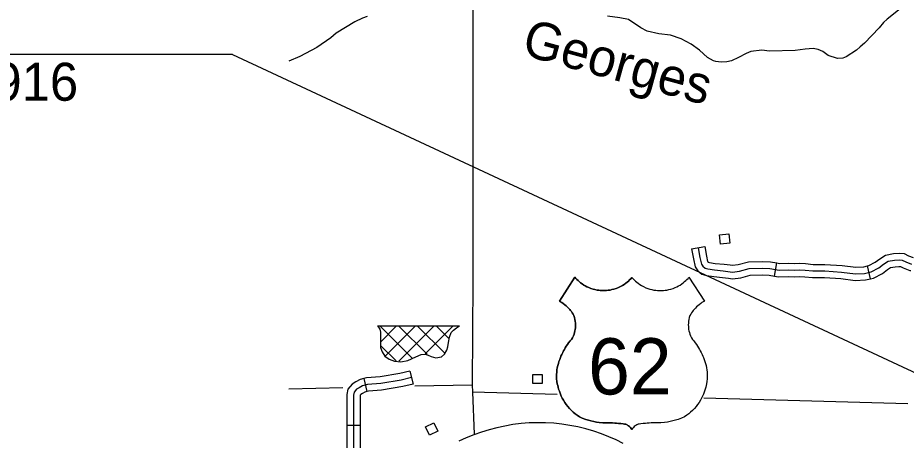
# Model space of a CAD drawing. Extents: x 1370130 to 1380143, y 377636 to 380256.
# Drawn here: x 1377914.6 to 1378335.4, y 378462.7 to 378662.8 of the extents above; entities that cross this region are included whole.
import ezdxf

# ---------------------------------------------------------------- set-up
doc = ezdxf.new("R2010")
doc.units = 0
for name, color, linetype in [('Level 15', 7, 'Continuous'), ('Level 22', 7, 'Continuous'), ('Level 32', 7, 'Continuous'), ('Level 35', 7, 'Continuous'), ('Level 4', 7, 'Continuous'), ('Level 45', 7, 'Continuous'), ('Level 49', 7, 'Continuous'), ('Level 5', 7, 'Continuous'), ('Level 56', 7, 'Continuous'), ('Level 57', 7, 'Continuous'), ('R_Draft', 7, 'Continuous')]:
    doc.layers.add(name, color=color, linetype=linetype)

msp = doc.modelspace()

# ---------------------------------------------------------------- linework, layer by layer
at = {"layer": 'Level 15'}
for p, q in [((1378141.58, 378468.6), (1378137.87, 378467.62)), ((1378145.34, 378469.44), (1378141.58, 378468.6)), ((1378149.13, 378470.1), (1378145.34, 378469.44)), ((1378152.96, 378470.61), (1378149.13, 378470.1)), ((1378156.85, 378470.92), (1378152.96, 378470.61)), ((1378160.73, 378471.03), (1378156.85, 378470.92)), ((1378164.6, 378470.97), (1378160.73, 378471.03)), ((1378168.46, 378470.73), (1378164.6, 378470.97)), ((1378172.31, 378470.32), (1378168.46, 378470.73)), ((1378176.13, 378469.75), (1378172.31, 378470.32)), ((1378179.92, 378469.01), (1378176.13, 378469.75)), ((1378183.68, 378468.09), (1378179.92, 378469.01)), ((1378187.39, 378467.01), (1378183.68, 378468.09)), ((1378127.03, 378463.78), (1378123.54, 378462.23)), ((1378130.58, 378465.2), (1378127.03, 378463.78)), ((1378134.2, 378466.48), (1378130.58, 378465.2)), ((1378137.87, 378467.62), (1378134.2, 378466.48)), ((1378191.01, 378465.76), (1378187.39, 378467.01)), ((1378194.53, 378464.38), (1378191.01, 378465.76)), ((1378197.97, 378462.87), (1378194.53, 378464.38)), ((1378201.34, 378461.25), (1378197.97, 378462.87))]:
    msp.add_line(p, q, dxfattribs=at)
at = {"layer": 'Level 22'}
for points in [[(1378205.49, 378539.84), (1378204.93, 378539.22), (1378204.41, 378538.68), (1378203.81, 378538.12), (1378203.16, 378537.56), (1378202.53, 378537.08), (1378201.77, 378536.55), (1378200.96, 378536.04), (1378200.03, 378535.53), (1378198.86, 378534.98), (1378197.95, 378534.63), (1378196.93, 378534.3), (1378196, 378534.06), (1378195.14, 378533.88), (1378194.23, 378533.74), (1378193.4, 378533.66), (1378192.26, 378533.6), (1378191.33, 378533.61), (1378190.52, 378533.66), (1378189.75, 378533.75), (1378188.97, 378533.86), (1378187.99, 378534.06), (1378187.08, 378534.3), (1378185.98, 378534.66), (1378185.04, 378535.03), (1378184.19, 378535.42), (1378183.41, 378535.83), (1378182.69, 378536.25), (1378181.89, 378536.78), (1378181.15, 378537.32), (1378180.52, 378537.84), (1378179.98, 378538.31), (1378179.43, 378538.84), (1378178.9, 378539.41), (1378178.46, 378539.9), (1378171.19, 378528.66), (1378171.71, 378528.35), (1378172.33, 378527.95), (1378172.92, 378527.53), (1378173.7, 378526.92), (1378174.32, 378526.39), (1378174.87, 378525.87), (1378175.44, 378525.3), (1378176.01, 378524.66), (1378176.43, 378524.16), (1378176.84, 378523.63), (1378177.25, 378523.05), (1378177.65, 378522.44), (1378178.02, 378521.73), (1378178.31, 378520.85), (1378178.52, 378519.99), (1378178.68, 378519.06), (1378178.77, 378518.2), (1378178.8, 378517.36), (1378178.78, 378516.58), (1378178.73, 378515.96), (1378178.62, 378515.19), (1378178.48, 378514.47), (1378178.28, 378513.69), (1378178.06, 378513.01), (1378177.76, 378512.24), (1378177.29, 378511.25), (1378176.8, 378510.47), (1378176.22, 378509.77), (1378175.51, 378508.86), (1378174.93, 378508.06), (1378174.39, 378507.26), (1378173.9, 378506.47), (1378173.48, 378505.77), (1378173.11, 378505.11), (1378172.7, 378504.32), (1378172.27, 378503.4), (1378171.87, 378502.51), (1378171.6, 378501.84), (1378171.28, 378500.98), (1378170.92, 378499.94), (1378170.64, 378499.07), (1378170.38, 378498.12), (1378170.13, 378497.01), (1378169.97, 378496.03), (1378169.85, 378495.01), (1378169.79, 378493.89), (1378169.78, 378492.84), (1378169.83, 378491.81), (1378169.96, 378490.6), (1378170.14, 378489.46), (1378170.33, 378488.59), (1378170.53, 378487.84), (1378170.78, 378486.98), (1378171.11, 378485.91), (1378171.59, 378484.62), (1378172, 378483.66), (1378172.48, 378482.68), (1378173.01, 378481.72), (1378173.7, 378480.62), (1378174.4, 378479.6), (1378175.09, 378478.72), (1378175.87, 378477.81), (1378176.87, 378476.77), (1378177.72, 378475.98), (1378178.6, 378475.25)], [(1378205.49, 378539.84), (1378206.04, 378539.22), (1378206.57, 378538.68), (1378207.17, 378538.12), (1378207.82, 378537.56), (1378208.44, 378537.08), (1378209.2, 378536.55), (1378210.01, 378536.04), (1378210.94, 378535.53), (1378212.12, 378534.98), (1378213.02, 378534.63), (1378214.04, 378534.3), (1378214.97, 378534.06), (1378215.83, 378533.88), (1378216.74, 378533.74), (1378217.58, 378533.66), (1378218.72, 378533.6), (1378219.65, 378533.61), (1378220.46, 378533.66), (1378221.23, 378533.75), (1378222.01, 378533.86), (1378222.99, 378534.06), (1378223.89, 378534.3), (1378225, 378534.66), (1378225.94, 378535.03), (1378226.78, 378535.42), (1378227.56, 378535.83), (1378228.28, 378536.25), (1378229.09, 378536.78), (1378229.82, 378537.32), (1378230.46, 378537.84), (1378231, 378538.31), (1378231.54, 378538.84), (1378232.08, 378539.41), (1378232.51, 378539.9), (1378239.78, 378528.66), (1378239.26, 378528.35), (1378238.64, 378527.95), (1378238.06, 378527.53), (1378237.28, 378526.92), (1378236.65, 378526.39), (1378236.1, 378525.87), (1378235.54, 378525.3), (1378234.96, 378524.66), (1378234.55, 378524.16), (1378234.14, 378523.63), (1378233.73, 378523.05), (1378233.32, 378522.44), (1378232.95, 378521.73), (1378232.67, 378520.85), (1378232.45, 378519.99), (1378232.29, 378519.06), (1378232.21, 378518.2), (1378232.18, 378517.36), (1378232.2, 378516.58), (1378232.25, 378515.96), (1378232.35, 378515.19), (1378232.5, 378514.47), (1378232.7, 378513.69), (1378232.92, 378513.01), (1378233.22, 378512.24), (1378233.69, 378511.25), (1378234.17, 378510.47), (1378234.76, 378509.77), (1378235.47, 378508.86), (1378236.05, 378508.06), (1378236.59, 378507.26), (1378237.08, 378506.47), (1378237.5, 378505.77), (1378237.86, 378505.11), (1378238.27, 378504.32), (1378238.71, 378503.4), (1378239.11, 378502.51), (1378239.38, 378501.84), (1378239.7, 378500.98), (1378240.05, 378499.94), (1378240.33, 378499.07), (1378240.6, 378498.12), (1378240.84, 378497.01), (1378241, 378496.03), (1378241.12, 378495.01), (1378241.19, 378493.89), (1378241.19, 378492.84), (1378241.15, 378491.81), (1378241.02, 378490.6), (1378240.83, 378489.46), (1378240.65, 378488.59), (1378240.45, 378487.84), (1378240.2, 378486.98), (1378239.87, 378485.91), (1378239.38, 378484.62), (1378238.97, 378483.66), (1378238.49, 378482.68), (1378237.96, 378481.72), (1378237.28, 378480.62), (1378236.57, 378479.6), (1378235.89, 378478.72), (1378235.11, 378477.81), (1378234.1, 378476.77), (1378233.25, 378475.98), (1378232.37, 378475.25)], [(1378178.6, 378475.25), (1378179.51, 378474.56), (1378180.61, 378473.84), (1378181.98, 378473.23), (1378183.59, 378472.61), (1378184.91, 378472.18), (1378186.09, 378471.85), (1378187.43, 378471.55), (1378188.68, 378471.31), (1378190.03, 378471.13), (1378191.73, 378470.98), (1378193.03, 378470.94), (1378194.14, 378470.94), (1378195.23, 378470.93), (1378196.31, 378470.9), (1378197.33, 378470.85), (1378198.23, 378470.79), (1378199.11, 378470.71), (1378200.24, 378470.59), (1378201.35, 378470.46), (1378202.01, 378470.36), (1378202.56, 378470.26), (1378203.22, 378469.98), (1378203.6, 378469.77), (1378203.93, 378469.55), (1378204.38, 378469.19), (1378204.81, 378468.75), (1378205.17, 378468.3), (1378205.49, 378467.77)], [(1378232.37, 378475.25), (1378231.46, 378474.56), (1378230.37, 378473.84), (1378228.99, 378473.23), (1378227.38, 378472.61), (1378226.07, 378472.18), (1378224.89, 378471.85), (1378223.55, 378471.55), (1378222.29, 378471.31), (1378220.95, 378471.13), (1378219.25, 378470.98), (1378217.95, 378470.94), (1378216.83, 378470.94), (1378215.75, 378470.93), (1378214.67, 378470.9), (1378213.64, 378470.85), (1378212.74, 378470.79), (1378211.86, 378470.71), (1378210.73, 378470.59), (1378209.63, 378470.46), (1378208.97, 378470.36), (1378208.42, 378470.26), (1378207.76, 378469.98), (1378207.38, 378469.77), (1378207.05, 378469.55), (1378206.59, 378469.19), (1378206.16, 378468.75), (1378205.81, 378468.3), (1378205.49, 378467.77)]]:
    msp.add_lwpolyline(points, dxfattribs=at)
at = {"layer": 'Level 32'}
for p, q in [((1378100.3, 378495.45), (1378101.83, 378489.34)), ((1378078.46, 378491.9), (1378079.99, 378485.79)), ((1378070.46, 378469.81), (1378076.76, 378469.83))]:
    msp.add_line(p, q, dxfattribs=at)
for points in [[(1378100.3, 378495.45), (1378095.64, 378494.29), (1378086.19, 378492.69), (1378079.8, 378492.23), (1378078.46, 378491.9)], [(1378078.46, 378491.9), (1378076.75, 378491.47), (1378074.67, 378490.33), (1378073.01, 378489.3), (1378070.95, 378486.97), (1378070.42, 378484.33), (1378070.46, 378469.81)], [(1378101.07, 378492.4), (1378096.28, 378491.2), (1378086.57, 378489.56), (1378080.29, 378489.11), (1378077.9, 378488.51), (1378076.26, 378487.61), (1378075.06, 378486.87), (1378073.87, 378485.52), (1378073.57, 378484.03), (1378073.69, 378435.94)], [(1378101.83, 378489.34), (1378096.93, 378488.12), (1378086.95, 378486.43), (1378080.79, 378485.99), (1378079.99, 378485.79)], [(1378079.99, 378485.79), (1378079.06, 378485.55), (1378077.85, 378484.89), (1378077.12, 378484.44), (1378076.79, 378484.07), (1378076.72, 378483.72), (1378076.76, 378469.83)], [(1378070.46, 378469.81), (1378070.51, 378447.63)], [(1378076.76, 378469.83), (1378076.81, 378447.65)]]:
    msp.add_lwpolyline(points, dxfattribs=at)
at = {"layer": 'Level 35'}
for points in [[(1378334.84, 378668.96), (1378326.28, 378662.13), (1378324.58, 378660.56), (1378322.53, 378658.04), (1378315.57, 378650.82), (1378313.62, 378649.06), (1378311.79, 378647.53), (1378306.87, 378644.41), (1378305.43, 378643.73), (1378302.88, 378643.55), (1378298.42, 378645.03), (1378295.84, 378646.87), (1378293.75, 378647.89), (1378291.3, 378648.31), (1378287.54, 378648), (1378282.78, 378647.29), (1378270.59, 378647.02), (1378266.93, 378647.43), (1378261.87, 378646.87), (1378259.56, 378645.99), (1378255.94, 378643.97), (1378252.6, 378642.46), (1378250.44, 378641.92), (1378247.76, 378641.78), (1378245.19, 378642.15), (1378244.04, 378642.45), (1378241.35, 378644.03), (1378237.49, 378647.47), (1378233.53, 378650.35), (1378228.83, 378652.88), (1378223.74, 378654.54), (1378218.3, 378655.19), (1378212.64, 378656.54), (1378209.69, 378658.12), (1378203.93, 378662.03), (1378199.79, 378662.81), (1378193.89, 378663.6)], [(1378080.18, 378663.43), (1378077.9, 378662.68), (1378074.32, 378660.87), (1378065.49, 378655.47), (1378062.84, 378653.35), (1378056.26, 378648.83)], [(1378056.26, 378648.83), (1378048.19, 378644.42), (1378043.04, 378642.28)]]:
    msp.add_lwpolyline(points, dxfattribs=at)
at = {"layer": 'Level 4'}
msp.add_lwpolyline([(1378130.37, 378730.62), (1378130.2, 378714.3), (1378130.12, 378707.22), (1378130.14, 378538.28), (1378129.82, 378489.02), (1378129.99, 378485.52), (1378130.85, 378465.63)], dxfattribs=at)
at = {"layer": 'Level 45'}
for p, q in [((1378233.77, 378553.38), (1378239.97, 378554.45)), ((1378273.02, 378540.48), (1378274.16, 378546.68)), ((1378318.47, 378539.18), (1378317.05, 378545.32))]:
    msp.add_line(p, q, dxfattribs=at)
for points in [[(1378233.77, 378553.38), (1378234.58, 378548.62), (1378235.46, 378544.84), (1378236.7, 378542.98), (1378238.67, 378541.42), (1378240.74, 378540.78), (1378244.2, 378540.25), (1378248.42, 378539.84), (1378251.26, 378539.48)], [(1378236.87, 378553.91), (1378237.67, 378549.24), (1378238.4, 378546.11), (1378239.04, 378545.14), (1378240.17, 378544.26), (1378241.45, 378543.86), (1378244.59, 378543.37), (1378248.77, 378542.97), (1378253.19, 378542.41), (1378256.41, 378542.81), (1378261.07, 378544.02), (1378267.34, 378544.18), (1378270.8, 378544.1), (1378275.14, 378543.29), (1378279.72, 378543.45), (1378282.46, 378543.29), (1378284.79, 378543.37), (1378287.52, 378543.29), (1378291.22, 378542.89), (1378296.77, 378542.89), (1378304.73, 378542.41), (1378311.4, 378541.6), (1378315.66, 378541.76), (1378318.8, 378542.49), (1378322.41, 378544.42), (1378324.67, 378546.11), (1378326.76, 378547.48), (1378329.81, 378548.04), (1378331.98, 378548.2), (1378333.51, 378548.04), (1378335.2, 378547.23), (1378337.85, 378546.19)], [(1378239.97, 378554.45), (1378240.76, 378549.87), (1378241.34, 378547.38), (1378241.38, 378547.31), (1378241.66, 378547.09), (1378242.17, 378546.93), (1378244.98, 378546.5), (1378249.12, 378546.1), (1378252.05, 378545.73)], [(1378317.05, 378545.32), (1378317.68, 378545.46), (1378320.72, 378547.08), (1378322.86, 378548.69), (1378325.56, 378550.46), (1378329.41, 378551.17), (1378332.03, 378551.36), (1378334.38, 378551.11), (1378336.45, 378550.12), (1378338.68, 378549.25)], [(1378252.05, 378545.73), (1378253.19, 378545.58), (1378255.81, 378545.91), (1378260.63, 378547.16), (1378267.34, 378547.33), (1378271.12, 378547.24), (1378274.16, 378546.68)], [(1378274.16, 378546.68), (1378275.37, 378546.45), (1378279.76, 378546.61), (1378282.49, 378546.45), (1378284.78, 378546.52), (1378287.74, 378546.44), (1378291.39, 378546.04), (1378295.71, 378546.04)], [(1378295.71, 378546.04), (1378296.86, 378546.04), (1378305.01, 378545.55), (1378311.53, 378544.76), (1378315.24, 378544.9), (1378317.05, 378545.32)], [(1378318.47, 378539.18), (1378319.91, 378539.51), (1378324.11, 378541.75), (1378326.47, 378543.53), (1378327.95, 378544.49), (1378330.21, 378544.91), (1378331.93, 378545.04), (1378332.64, 378544.96), (1378333.94, 378544.34), (1378337.02, 378543.13), (1378337.52, 378543.05)], [(1378251.26, 378539.48), (1378253.19, 378539.23), (1378257, 378539.71), (1378261.51, 378540.88), (1378267.35, 378541.03), (1378270.47, 378540.95), (1378273.02, 378540.48)], [(1378273.02, 378540.48), (1378274.91, 378540.13), (1378279.69, 378540.3), (1378282.42, 378540.14), (1378284.8, 378540.22), (1378287.3, 378540.15), (1378291.05, 378539.74), (1378295.71, 378539.74)], [(1378295.71, 378539.74), (1378296.67, 378539.74), (1378304.44, 378539.27), (1378311.27, 378538.45), (1378316.08, 378538.63), (1378318.47, 378539.18)]]:
    msp.add_lwpolyline(points, dxfattribs=at)
at = {"layer": 'Level 49'}
for points in [[(1378178.6, 378475.25), (1378177.72, 378475.98), (1378176.87, 378476.77), (1378175.87, 378477.81), (1378175.09, 378478.72), (1378174.4, 378479.6), (1378173.7, 378480.62), (1378173.01, 378481.72), (1378172.48, 378482.68), (1378172, 378483.66), (1378171.59, 378484.62), (1378171.11, 378485.91), (1378170.78, 378486.98), (1378170.53, 378487.84), (1378170.33, 378488.59), (1378170.14, 378489.46), (1378169.96, 378490.6), (1378169.83, 378491.81), (1378169.78, 378492.84), (1378169.79, 378493.89), (1378169.85, 378495.01), (1378169.97, 378496.03), (1378170.13, 378497.01), (1378170.38, 378498.12), (1378170.64, 378499.07), (1378170.92, 378499.94), (1378171.28, 378500.98), (1378171.6, 378501.84), (1378171.87, 378502.51), (1378172.27, 378503.4), (1378172.7, 378504.32), (1378173.11, 378505.11), (1378173.48, 378505.77), (1378173.9, 378506.47), (1378174.39, 378507.26), (1378174.93, 378508.06), (1378175.51, 378508.86), (1378176.22, 378509.77), (1378176.8, 378510.47), (1378177.29, 378511.25), (1378177.76, 378512.24), (1378178.06, 378513.01), (1378178.28, 378513.69), (1378178.48, 378514.47), (1378178.62, 378515.19), (1378178.73, 378515.96), (1378178.78, 378516.58), (1378178.8, 378517.36), (1378178.77, 378518.2), (1378178.68, 378519.06), (1378178.52, 378519.99), (1378178.31, 378520.85), (1378178.02, 378521.73), (1378177.65, 378522.44), (1378177.25, 378523.05), (1378176.84, 378523.63), (1378176.43, 378524.16), (1378176.01, 378524.66), (1378175.44, 378525.3), (1378174.87, 378525.87), (1378174.32, 378526.39), (1378173.7, 378526.92), (1378172.92, 378527.53), (1378172.33, 378527.95), (1378171.71, 378528.35), (1378171.19, 378528.66), (1378178.46, 378539.9), (1378178.9, 378539.41), (1378179.43, 378538.84), (1378179.98, 378538.31), (1378180.52, 378537.84), (1378181.15, 378537.32), (1378181.89, 378536.78), (1378182.69, 378536.25), (1378183.41, 378535.83), (1378184.19, 378535.42), (1378185.04, 378535.03), (1378185.98, 378534.66), (1378187.08, 378534.3), (1378187.99, 378534.06), (1378188.97, 378533.86), (1378189.75, 378533.75), (1378190.52, 378533.66), (1378191.33, 378533.61), (1378192.26, 378533.6), (1378193.4, 378533.66), (1378194.23, 378533.74), (1378195.14, 378533.88), (1378196, 378534.06), (1378196.93, 378534.3), (1378197.95, 378534.63), (1378198.86, 378534.98), (1378200.03, 378535.53), (1378200.96, 378536.04), (1378201.77, 378536.55), (1378202.53, 378537.08), (1378203.16, 378537.56), (1378203.81, 378538.12), (1378204.41, 378538.68), (1378204.93, 378539.22), (1378205.49, 378539.84)], [(1378205.49, 378539.84), (1378206.04, 378539.22), (1378206.57, 378538.68), (1378207.17, 378538.12), (1378207.82, 378537.56), (1378208.44, 378537.08), (1378209.2, 378536.55), (1378210.01, 378536.04), (1378210.94, 378535.53), (1378212.12, 378534.98), (1378213.02, 378534.63), (1378214.04, 378534.3), (1378214.97, 378534.06), (1378215.83, 378533.88), (1378216.74, 378533.74), (1378217.58, 378533.66), (1378218.72, 378533.6), (1378219.65, 378533.61), (1378220.46, 378533.66), (1378221.23, 378533.75), (1378222.01, 378533.86), (1378222.99, 378534.06), (1378223.89, 378534.3), (1378225, 378534.66), (1378225.94, 378535.03), (1378226.78, 378535.42), (1378227.56, 378535.83), (1378228.28, 378536.25), (1378229.09, 378536.78), (1378229.82, 378537.32), (1378230.46, 378537.84), (1378231, 378538.31), (1378231.54, 378538.84), (1378232.08, 378539.41), (1378232.51, 378539.9), (1378239.78, 378528.66), (1378239.26, 378528.35), (1378238.64, 378527.95), (1378238.06, 378527.53), (1378237.28, 378526.92), (1378236.65, 378526.39), (1378236.1, 378525.87), (1378235.54, 378525.3), (1378234.96, 378524.66), (1378234.55, 378524.16), (1378234.14, 378523.63), (1378233.73, 378523.05), (1378233.32, 378522.44), (1378232.95, 378521.73), (1378232.67, 378520.85), (1378232.45, 378519.99), (1378232.29, 378519.06), (1378232.21, 378518.2), (1378232.18, 378517.36), (1378232.2, 378516.58), (1378232.25, 378515.96), (1378232.35, 378515.19), (1378232.5, 378514.47), (1378232.7, 378513.69), (1378232.92, 378513.01), (1378233.22, 378512.24), (1378233.69, 378511.25), (1378234.17, 378510.47), (1378234.76, 378509.77), (1378235.47, 378508.86), (1378236.05, 378508.06), (1378236.59, 378507.26), (1378237.08, 378506.47), (1378237.5, 378505.77), (1378237.86, 378505.11), (1378238.27, 378504.32), (1378238.71, 378503.4), (1378239.11, 378502.51), (1378239.38, 378501.84), (1378239.7, 378500.98), (1378240.05, 378499.94), (1378240.33, 378499.07), (1378240.6, 378498.12), (1378240.84, 378497.01), (1378241, 378496.03), (1378241.12, 378495.01), (1378241.19, 378493.89), (1378241.19, 378492.84), (1378241.15, 378491.81), (1378241.02, 378490.6), (1378240.83, 378489.46), (1378240.65, 378488.59), (1378240.45, 378487.84), (1378240.2, 378486.98), (1378239.87, 378485.91), (1378239.38, 378484.62), (1378238.97, 378483.66), (1378238.49, 378482.68), (1378237.96, 378481.72), (1378237.28, 378480.62), (1378236.57, 378479.6), (1378235.89, 378478.72), (1378235.11, 378477.81), (1378234.1, 378476.77), (1378233.25, 378475.98), (1378232.37, 378475.25)], [(1378205.49, 378467.77), (1378205.17, 378468.3), (1378204.81, 378468.75), (1378204.38, 378469.19), (1378203.93, 378469.55), (1378203.6, 378469.77), (1378203.22, 378469.98), (1378202.56, 378470.26), (1378202.01, 378470.36), (1378201.35, 378470.46), (1378200.24, 378470.59), (1378199.11, 378470.71), (1378198.23, 378470.79), (1378197.33, 378470.85), (1378196.31, 378470.9), (1378195.23, 378470.93), (1378194.14, 378470.94), (1378193.03, 378470.94), (1378191.73, 378470.98), (1378190.03, 378471.13), (1378188.68, 378471.31), (1378187.43, 378471.55), (1378186.09, 378471.85), (1378184.91, 378472.18), (1378183.59, 378472.61), (1378181.98, 378473.23), (1378180.61, 378473.84), (1378179.51, 378474.56), (1378178.6, 378475.25)], [(1378232.37, 378475.25), (1378231.46, 378474.56), (1378230.37, 378473.84), (1378228.99, 378473.23), (1378227.38, 378472.61), (1378226.07, 378472.18), (1378224.89, 378471.85), (1378223.55, 378471.55), (1378222.29, 378471.31), (1378220.95, 378471.13), (1378219.25, 378470.98), (1378217.95, 378470.94), (1378216.83, 378470.94), (1378215.75, 378470.93), (1378214.67, 378470.9), (1378213.64, 378470.85), (1378212.74, 378470.79), (1378211.86, 378470.71), (1378210.73, 378470.59), (1378209.63, 378470.46), (1378208.97, 378470.36), (1378208.42, 378470.26), (1378207.76, 378469.98), (1378207.38, 378469.77), (1378207.05, 378469.55), (1378206.59, 378469.19), (1378206.16, 378468.75), (1378205.81, 378468.3), (1378205.49, 378467.77)]]:
    msp.add_lwpolyline(points, dxfattribs=at)
at = {"layer": 'Level 5'}
for points in [[(1378102.72, 378488.43), (1378129.82, 378489.02)], [(1378043.04, 378487.14), (1378068.6, 378487.69)], [(1378170.09, 378484.45), (1378129.99, 378485.52)], [(1378336.17, 378480.01), (1378239.5, 378482.59)]]:
    msp.add_lwpolyline(points, dxfattribs=at)
at = {"layer": 'Level 56'}
for points in [[(1378251.4, 378560.43), (1378251.8, 378556.07), (1378247.44, 378555.67), (1378247.03, 378560.02)], [(1378158.58, 378489.52), (1378158.58, 378493.89), (1378162.96, 378493.89), (1378162.96, 378489.52)], [(1378109.62, 378465.08), (1378107.69, 378469.01), (1378111.63, 378470.94), (1378113.56, 378467.01)]]:
    msp.add_lwpolyline(points, close=True, dxfattribs=at)
at = {"layer": 'Level 57'}
for p, q in [((1378084.99, 378516.85), (1378123.79, 378516.85)), ((1378101.38, 378501.59), (1378086.27, 378516.69)), ((1378086.58, 378509.4), (1378093.89, 378516.71)), ((1378088.75, 378502.66), (1378102.75, 378516.66)), ((1378108.44, 378503.43), (1378095.13, 378516.74)), ((1378095.15, 378500.14), (1378111.73, 378516.73)), ((1378116.81, 378503.97), (1378104.14, 378516.64)), ((1378107.57, 378503.66), (1378120.56, 378516.65)), ((1378118.77, 378510.92), (1378113.03, 378516.66)), ((1378093.79, 378500.26), (1378086.72, 378507.34))]:
    msp.add_line(p, q, dxfattribs=at)
msp.add_lwpolyline([(1378084.99, 378516.85), (1378085.54, 378516.25), (1378086.06, 378515.32), (1378086.41, 378513.93), (1378086.41, 378511.84), (1378086.46, 378509.11), (1378086.46, 378506.68), (1378087.16, 378504.65), (1378088.49, 378502.56), (1378090.58, 378501.05), (1378093.02, 378500.13), (1378095.97, 378499.84), (1378099.34, 378500.47), (1378103.22, 378502.21), (1378105.6, 378503.26), (1378107.63, 378503.43), (1378109.02, 378503.03), (1378110.41, 378502.33), (1378112.67, 378501.81), (1378115.28, 378502.27), (1378116.67, 378503.43), (1378117.83, 378505.34), (1378118.35, 378507.03), (1378118.64, 378509), (1378119.11, 378511.49), (1378119.92, 378513.75), (1378121.02, 378514.8), (1378122.41, 378515.9), (1378123.79, 378516.85)], dxfattribs=at)
at = {"layer": 'R_Draft'}
for q in [(1377721.32, 378645.48), (1378559.62, 378392.03)]:
    msp.add_line((1378016.31, 378645.48), q, dxfattribs=at)

# ---------------------------------------------------------------- texts
at = {"layer": 'Level 22'}
msp.add_text('62', height=26.611, dxfattribs=at).set_placement((1378184.71, 378484.41))
at = {"layer": 'Level 35'}
msp.add_text('Georges', height=17.741, rotation=344.6424, dxfattribs=at).set_placement((1378152.65, 378645.49))
at = {"layer": 'R_Draft'}
msp.add_text('BEGIN JOB 009916', height=18, rotation=0.0006, dxfattribs=at).set_placement((1377727.85, 378623.53))

doc.saveas('drawing.dxf')
